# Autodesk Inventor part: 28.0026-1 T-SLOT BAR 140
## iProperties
Created: 2006-12
Part Number: 28.0026-1 T-SLOT BAR 140
Material: Steel
Document SubType Name: Modeling
Designer: Andy Moles
Density: 7.85 g/cm^3
Author: Andy Moles
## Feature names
1. Extrusion1
2. Hole1
